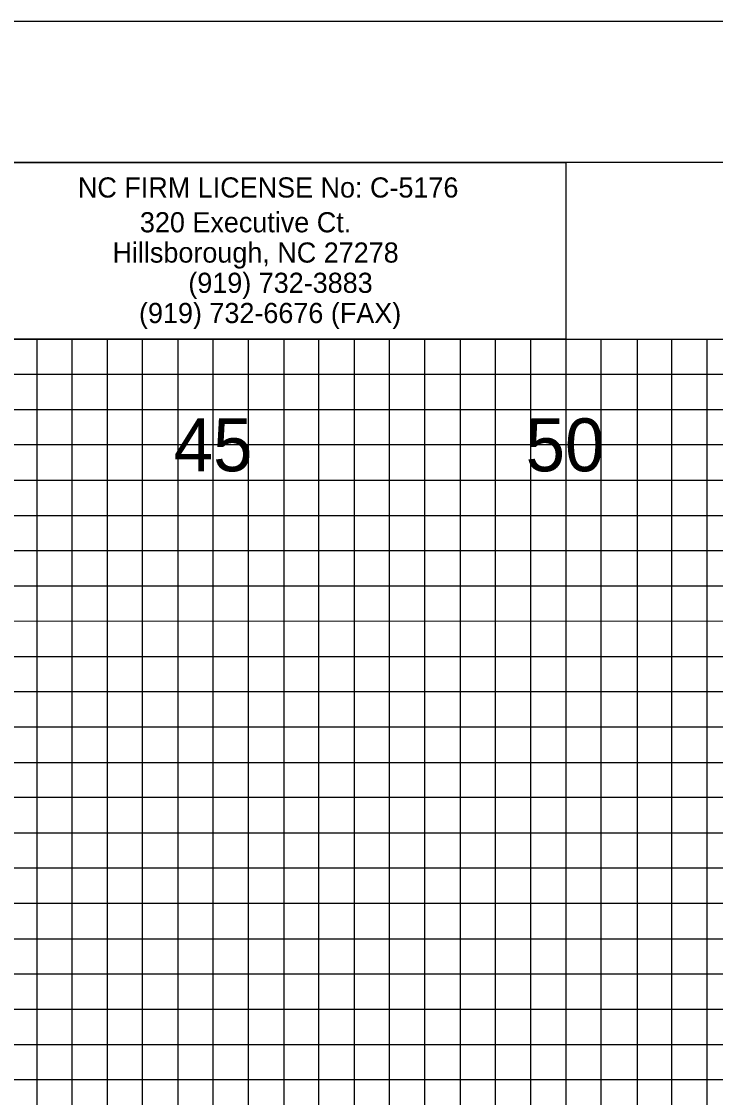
# Model space of a CAD drawing. Extents: x -7 to 162, y -2 to 107.
# Drawn here: x 122.28 to 132.12, y 91.75 to 107 of the extents above; entities that cross this region are included whole.
import ezdxf

# ---------------------------------------------------------------- set-up
doc = ezdxf.new("R2010")
doc.units = 0
for name, color, linetype in [('Prop DSN Text', 7, 'Continuous'), ('Prop XS Offset Labels', 7, 'Continuous'), ('Sheet Block Title CELL', 7, 'Continuous'), ('Sheet Cross Section CELL', 7, 'Continuous'), ('Sheet Cross Section Grid Major CELL', 7, 'Continuous'), ('Sheet Cross Section Grid Middle CELL', 7, 'Continuous'), ('Sheet Cross Section Grid Minor 1 CELL', 7, 'Continuous'), ('Sheet Cross Section Grid Minor 2 CELL', 7, 'Continuous'), ('Sheet Plot Border Inside CELL', 7, 'Continuous'), ('Sheet Plot Border Outside CELL', 7, 'Continuous')]:
    doc.layers.add(name, color=color, linetype=linetype)

msp = doc.modelspace()

# ---------------------------------------------------------------- linework, layer by layer
at = {"layer": 'Sheet Block Title CELL'}
msp.add_lwpolyline([(110.951, 105), (130, 105), (130, 102.5), (110.951, 102.5)], close=True, dxfattribs=at)
at = {"layer": 'Sheet Cross Section CELL'}
for points in [[(160, 105), (0, 105), (0, 0), (160, 0)], [(140, 105), (130, 105), (130, 102.5), (140, 102.5)]]:
    msp.add_lwpolyline(points, close=True, dxfattribs=at)
at = {"layer": 'Sheet Cross Section Grid Major CELL'}
for p, q in [((125, 105), (120, 105)), ((130, 105), (130, 0)), ((125, 0), (125, 102.5))]:
    msp.add_line(p, q, dxfattribs=at)
for points in [[(160, 102.5), (160, 95), (0, 95)], [(0, 100), (160, 100)]]:
    msp.add_lwpolyline(points, dxfattribs=at)
at = {"layer": 'Sheet Cross Section Grid Middle CELL'}
for points in [[(117.5, 105), (122.5, 105)], [(127.5, 105), (129.965, 105), (130, 105), (130, 102.5), (132.495, 102.5), (132.495, 0), (137.5, 0), (137.5, 102.5), (140, 102.5)], [(0, 102.5), (137.5, 102.5)], [(0, 92.5), (160, 92.5), (160, 102.5)], [(122.5, 102.5), (122.5, 0), (127.5, 0), (127.5, 102.5)], [(160, 97.5), (0, 97.5)]]:
    msp.add_lwpolyline(points, dxfattribs=at)
at = {"layer": 'Sheet Cross Section Grid Minor 1 CELL'}
for p, q in [((130, 104.5), (130, 103.99)), ((130, 103.5), (130, 102.945)), ((0, 102), (160, 102))]:
    msp.add_line(p, q, dxfattribs=at)
for points in [[(0, 101.5), (135, 101.5), (160, 101.5)], [(160, 101), (0, 101)], [(0, 100.5), (160, 100.5)], [(160, 99.5), (0, 99.5)], [(0, 99), (160, 99)], [(160, 98.5), (0, 98.49)], [(0, 98), (160, 98)], [(160, 97), (0, 97)], [(0, 96.5), (160, 96.5), (160, 96), (0, 96)], [(0, 95.5), (160, 95.5), (160, 94.5), (0, 94.5)], [(0, 94), (160, 94), (160, 93.5), (0, 93.5)], [(0, 93), (160, 93), (160, 92), (0, 92)]]:
    msp.add_lwpolyline(points, dxfattribs=at)
at = {"layer": 'Sheet Cross Section Grid Minor 2 CELL'}
for points in [[(123, 105), (123.5, 105)], [(124, 105), (124.5, 105)], [(125.5, 105), (126, 105)], [(126.5, 105), (127, 105)], [(128, 105), (128.5, 105)], [(129, 105), (129.5, 105)], [(122.5, 0), (123, 0), (123, 102.5)], [(123.5, 102.5), (123.5, 0)], [(123.5, 0), (124, 0), (124, 102.5)], [(124.5, 102.5), (124.5, 0)], [(125, 0), (125.5, 0), (125.5, 102.5)], [(126, 102.5), (126, 0)], [(126, 0), (126.5, 0), (126.5, 102.5)], [(127, 102.5), (127, 0)], [(127.5, 0), (128, 0), (128, 102.5)], [(128.5, 102.5), (128.5, 0)], [(128.5, 0), (129, 0), (129, 102.5)], [(129.5, 102.5), (129.5, 0)], [(130, 0), (130.5, 0), (130.5, 102.5), (131.01, 102.5), (131.01, 0)], [(131, 0), (131.5, 0), (131.5, 102.5), (131.995, 102.5), (131.995, 0)]]:
    msp.add_lwpolyline(points, dxfattribs=at)
at = {"layer": 'Sheet Plot Border Inside CELL'}
msp.add_lwpolyline([(-5.4, -0.5), (161.2, -0.5), (161.2, 105), (-5.4, 105)], close=True, dxfattribs=at)
at = {"layer": 'Sheet Plot Border Outside CELL'}
msp.add_lwpolyline([(-6.7, -2.5), (161.65, -2.5), (161.65, 107), (-6.7, 107)], close=True, dxfattribs=at)

# ---------------------------------------------------------------- texts
at = {"layer": 'Prop DSN Text'}
msp.add_text('NC FIRM LICENSE No: C-5176', height=0.28573, dxfattribs=at).set_placement((123.083, 104.505))
for s, p in [('320 Executive Ct.', (123.962, 104.012)), ('Hillsborough, NC 27278', (123.573, 103.583)), ('(919) 732-3883', (124.648, 103.154)), ('(919) 732-6676 (FAX)', (123.949, 102.726))]:
    msp.add_text(s, height=0.28573, rotation=360, dxfattribs=at).set_placement(p)
at = {"layer": 'Prop XS Offset Labels'}
for s, p in [('45', (124.441, 100.625)), ('50', (129.429, 100.625))]:
    msp.add_text(s, height=0.75, dxfattribs=at).set_placement(p)

doc.saveas('drawing.dxf')
